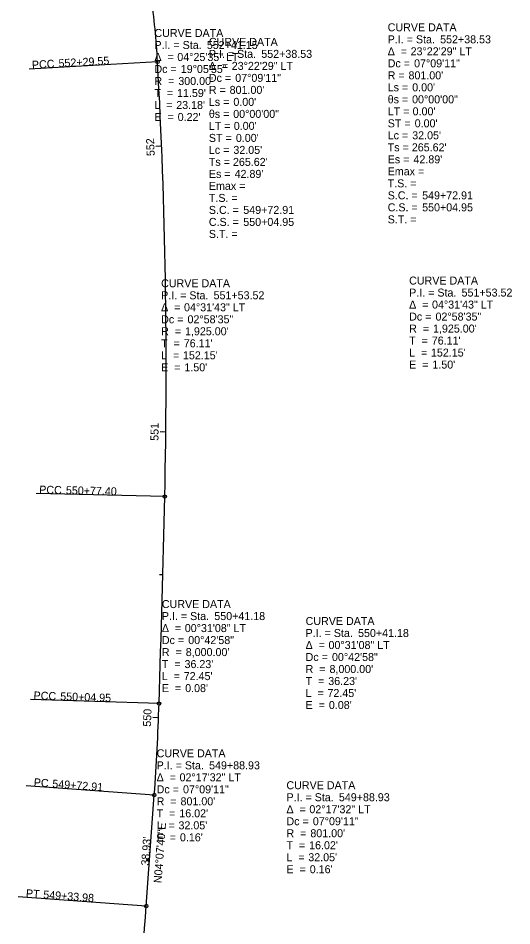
# Model space of a CAD drawing. Extents: x 1922787 to 1923078, y 359089 to 360354.
# Drawn here: x 1922882.9 to 1923055.9, y 359406.6 to 359724.2 of the extents above; entities that cross this region are included whole.
import ezdxf

# ---------------------------------------------------------------- set-up
doc = ezdxf.new("R2010")
doc.units = 0
for name, color, linetype in [('GE_P_Alignment', 7, 'Continuous'), ('GE_P_Alignment_1000_Curve_Data', 7, 'Continuous'), ('GE_P_Alignment_1000_Stations', 7, 'Continuous'), ('GE_P_Alignment_100_Curve_Data', 7, 'Continuous'), ('GE_P_Alignment_100_Stations', 7, 'Continuous'), ('GE_P_Alignment_500_Curve_Data', 7, 'Continuous'), ('GE_P_Alignment_500_Stations', 7, 'Continuous')]:
    doc.layers.add(name, color=color, linetype=linetype)

msp = doc.modelspace()

# ---------------------------------------------------------------- linework, layer by layer
at = {"layer": 'GE_P_Alignment'}
msp.add_line((1922927.81, 359413.55), (1922930.61, 359452.38), dxfattribs=at)
for centre, radius, start, end in [((1922632.22, 359692.09), 300, 3.2119, 7.6383), ((1921009.78, 359601.04), 1925, 358.68333, 3.21194), ((1914936.38, 359740.63), 8000, 358.164444, 358.683333), ((1922131.69, 359510.04), 801, 355.87222, 358.16444), ((1921930.4, 359485.54), 1000, 352.30833, 355.87222)]:
    msp.add_arc(centre, radius, start, end, dxfattribs=at)
at = {"layer": 'GE_P_Alignment_1000_Stations'}
for p, q in [((1922931.75, 359708.9), (1922886.82, 359706.38)), ((1922934.27, 359556.81), (1922889.28, 359557.84)), ((1922932.28, 359484.38), (1922887.3, 359485.83)), ((1922932.1, 359479.44), (1922930.1, 359479.51)), ((1922930.61, 359452.38), (1922885.73, 359455.62)), ((1922927.81, 359413.55), (1922882.92, 359416.79))]:
    msp.add_line(p, q, dxfattribs=at)
for centre in [(1922931.75, 359708.9), (1922934.27, 359556.81), (1922932.28, 359484.38), (1922930.61, 359452.38), (1922927.81, 359413.55)]:
    msp.add_circle(centre, 0.6, dxfattribs=at)
at = {"layer": 'GE_P_Alignment_100_Stations'}
for p, q in [((1922931.75, 359708.9), (1922886.82, 359706.38)), ((1922933.18, 359679.38), (1922931.18, 359679.3)), ((1922934.66, 359579.4), (1922932.66, 359579.42)), ((1922934.27, 359556.81), (1922889.28, 359557.84)), ((1922933.59, 359529.41), (1922932.39, 359529.45)), ((1922932.28, 359484.38), (1922887.3, 359485.83)), ((1922932.1, 359479.44), (1922930.1, 359479.51)), ((1922930.61, 359452.38), (1922885.73, 359455.62)), ((1922928.96, 359429.54), (1922927.76, 359429.62)), ((1922927.81, 359413.55), (1922882.92, 359416.79))]:
    msp.add_line(p, q, dxfattribs=at)
for centre in [(1922931.75, 359708.9), (1922934.27, 359556.81), (1922932.28, 359484.38), (1922930.61, 359452.38), (1922927.81, 359413.55)]:
    msp.add_circle(centre, 0.6, dxfattribs=at)
at = {"layer": 'GE_P_Alignment_500_Stations'}
for p, q in [((1922931.75, 359708.9), (1922886.82, 359706.38)), ((1922933.18, 359679.38), (1922931.98, 359679.33)), ((1922934.66, 359579.4), (1922933.46, 359579.42)), ((1922934.27, 359556.81), (1922889.28, 359557.84)), ((1922932.28, 359484.38), (1922887.3, 359485.83)), ((1922932.1, 359479.44), (1922930.1, 359479.51)), ((1922930.61, 359452.38), (1922885.73, 359455.62)), ((1922927.81, 359413.55), (1922882.92, 359416.79))]:
    msp.add_line(p, q, dxfattribs=at)
for centre in [(1922931.75, 359708.9), (1922934.27, 359556.81), (1922932.28, 359484.38), (1922930.61, 359452.38), (1922927.81, 359413.55)]:
    msp.add_circle(centre, 0.6, dxfattribs=at)

# ---------------------------------------------------------------- texts
at = {"layer": 'GE_P_Alignment_1000_Curve_Data'}
for s, p in [('CURVE DATA', (1922930.66, 359717.63)), ('P.I. = Sta. ', (1922930.66, 359713.43)), ('552+41.15', (1922949.03, 359713.43)), ('CURVE DATA', (1922949.73, 359714.52)), ('P.I. = Sta. ', (1922949.73, 359710.32)), ('552+38.53', (1922968.1, 359710.32)), ('Δ  = ', (1922930.66, 359709.23)), ('04°25\'35" LT', (1922938.68, 359709.23)), ('Dc = ', (1922930.66, 359705.03)), ('19°05\'55"', (1922939.9, 359705.03)), ('Δ  = ', (1922949.73, 359706.12)), ('23°22\'29" LT', (1922957.75, 359706.12)), ('R  = ', (1922930.66, 359700.83)), ("300.00'", (1922939.03, 359700.83)), ('Dc = ', (1922949.73, 359701.92)), ('07°09\'11"', (1922958.97, 359701.92)), ('R = ', (1922949.73, 359697.72)), ("801.00'", (1922957.01, 359697.72)), ('T  = ', (1922930.66, 359696.63)), ("11.59'", (1922938.59, 359696.63)), ('L  = ', (1922930.66, 359692.43)), ("23.18'", (1922938.3, 359692.43)), ('Ls = ', (1922949.73, 359693.52)), ("0.00'", (1922958.32, 359693.52)), ('E  = ', (1922930.66, 359688.23)), ("0.22'", (1922938.81, 359688.23)), ('θs = ', (1922949.73, 359689.32)), ('00°00\'00"', (1922958.26, 359689.32)), ('LT = ', (1922949.73, 359685.12)), ("0.00'", (1922958.46, 359685.12)), ('ST = ', (1922949.73, 359680.92)), ("0.00'", (1922959.19, 359680.92)), ('Lc = ', (1922949.73, 359676.72)), ("32.05'", (1922958.32, 359676.72)), ('Ts = ', (1922949.73, 359672.52)), ("265.62'", (1922958.17, 359672.52)), ('Es = ', (1922949.73, 359668.32)), ("42.89'", (1922958.75, 359668.32)), ('Emax = ', (1922949.73, 359664.12)), ('T.S. = ', (1922949.73, 359659.92)), ('S.C. = ', (1922949.73, 359655.72)), ('549+72.91', (1922961.79, 359655.72)), ('C.S. = ', (1922949.73, 359651.52)), ('550+04.95', (1922961.79, 359651.52)), ('S.T. = ', (1922949.73, 359647.32)), ('CURVE DATA', (1922933.01, 359630.05)), ('P.I. = Sta. ', (1922933.01, 359625.85)), ('551+53.52', (1922951.38, 359625.85)), ('Δ  = ', (1922933.01, 359621.65)), ('04°31\'43" LT', (1922941.03, 359621.65)), ('02°58\'35"', (1922942.25, 359617.45)), ('Dc = ', (1922933.01, 359617.45)), ('R  = ', (1922933.01, 359613.25)), ("1,925.00'", (1922941.38, 359613.25)), ('T  = ', (1922933.01, 359609.05)), ("76.11'", (1922940.94, 359609.05)), ('L  = ', (1922933.01, 359604.85)), ("152.15'", (1922940.66, 359604.85)), ('E  = ', (1922933.01, 359600.65)), ("1.50'", (1922941.16, 359600.65)), ('CURVE DATA', (1922933.27, 359517.8)), ('P.I. = Sta. ', (1922933.27, 359513.6)), ('550+41.18', (1922951.64, 359513.6)), ('Δ  = ', (1922933.27, 359509.4)), ('00°31\'08" LT', (1922941.3, 359509.4)), ('Dc = ', (1922933.27, 359505.2)), ('00°42\'58"', (1922942.51, 359505.2)), ('R  = ', (1922933.27, 359501)), ("8,000.00'", (1922941.64, 359501)), ('T  = ', (1922933.27, 359496.8)), ("36.23'", (1922941.21, 359496.8)), ('L  = ', (1922933.27, 359492.6)), ("72.45'", (1922940.92, 359492.6)), ('E  = ', (1922933.27, 359488.4)), ("0.08'", (1922941.43, 359488.4)), ('CURVE DATA', (1922931.44, 359465.58)), ('P.I. = Sta. ', (1922931.44, 359461.38)), ('549+88.93', (1922949.81, 359461.38)), ('Δ  = ', (1922931.44, 359457.18)), ('02°17\'32" LT', (1922939.47, 359457.18)), ('Dc = ', (1922931.44, 359452.98)), ('07°09\'11"', (1922940.68, 359452.98)), ('R  = ', (1922931.44, 359448.78)), ("801.00'", (1922939.81, 359448.78)), ('T  = ', (1922931.44, 359444.58)), ("16.02'", (1922939.38, 359444.58)), ('L  = ', (1922931.44, 359440.38)), ("32.05'", (1922939.09, 359440.38)), ('E  = ', (1922931.44, 359436.18)), ("0.16'", (1922939.6, 359436.18))]:
    msp.add_text(s, height=2.8, dxfattribs=at).set_placement(p)
for s, p in [('N04°07\'40"E', (1922933.19, 359421.47)), ("38.93'", (1922928.77, 359427.59))]:
    msp.add_text(s, height=2.8, rotation=85.8722, dxfattribs=at).set_placement(p)
at = {"layer": 'GE_P_Alignment_1000_Stations'}
for s, rotation, p in [('PCC', 3.2119, (1922887.82, 359706.48)), ('552+29.55', 3.2119, (1922897.15, 359707)), ('PCC', 358.6833, (1922890.29, 359557.86)), ('550+77.40', 358.6833, (1922899.64, 359557.65)), ('PCC', 358.1644, (1922888.3, 359485.84)), ('550+04.95', 358.1644, (1922897.64, 359485.54)), ('550', 87.8103, (1922929.43, 359476.26)), ('PC', 355.8722, (1922888.32, 359455.48)), ('549+72.91', 355.8722, (1922894.82, 359455.01)), ('PT', 355.8722, (1922885.57, 359416.65)), ('549+33.98', 355.8722, (1922891.64, 359416.21))]:
    msp.add_text(s, height=2.8, rotation=rotation, dxfattribs=at).set_placement(p)
at = {"layer": 'GE_P_Alignment_100_Curve_Data'}
for s, p in [('CURVE DATA', (1923012.37, 359719.62)), ('P.I. = Sta. ', (1923012.37, 359715.42)), ('552+38.53', (1923030.74, 359715.42)), ('Δ  = ', (1923012.37, 359711.22)), ('23°22\'29" LT', (1923020.4, 359711.22)), ('Dc = ', (1923012.37, 359707.02)), ('07°09\'11"', (1923021.61, 359707.02)), ('R = ', (1923012.37, 359702.82)), ("801.00'", (1923019.66, 359702.82)), ('Ls = ', (1923012.37, 359698.62)), ("0.00'", (1923020.96, 359698.62)), ('θs = ', (1923012.37, 359694.42)), ('00°00\'00"', (1923020.91, 359694.42)), ('LT = ', (1923012.37, 359690.22)), ("0.00'", (1923021.1, 359690.22)), ('ST = ', (1923012.37, 359686.02)), ("0.00'", (1923021.83, 359686.02)), ('Lc = ', (1923012.37, 359681.82)), ("32.05'", (1923020.96, 359681.82)), ('Ts = ', (1923012.37, 359677.62)), ("265.62'", (1923020.82, 359677.62)), ('Es = ', (1923012.37, 359673.42)), ("42.89'", (1923021.4, 359673.42)), ('Emax = ', (1923012.37, 359669.22)), ('T.S. = ', (1923012.37, 359665.02)), ('S.C. = ', (1923012.37, 359660.82)), ('549+72.91', (1923024.44, 359660.82)), ('C.S. = ', (1923012.37, 359656.62)), ('550+04.95', (1923024.44, 359656.62)), ('S.T. = ', (1923012.37, 359652.42)), ('CURVE DATA', (1923019.88, 359631)), ('P.I. = Sta. ', (1923019.88, 359626.8)), ('551+53.52', (1923038.25, 359626.8)), ('Δ  = ', (1923019.88, 359622.6)), ('04°31\'43" LT', (1923027.9, 359622.6)), ('Dc = ', (1923019.88, 359618.4)), ('02°58\'35"', (1923029.12, 359618.4)), ('R  = ', (1923019.88, 359614.2)), ("1,925.00'", (1923028.25, 359614.2)), ('T  = ', (1923019.88, 359610)), ("76.11'", (1923027.81, 359610)), ('L  = ', (1923019.88, 359605.8)), ("152.15'", (1923027.53, 359605.8)), ('E  = ', (1923019.88, 359601.6)), ("1.50'", (1923028.03, 359601.6)), ('CURVE DATA', (1922983.62, 359511.87)), ('P.I. = Sta. ', (1922983.62, 359507.67)), ('550+41.18', (1923001.99, 359507.67)), ('Δ  = ', (1922983.62, 359503.47)), ('00°31\'08" LT', (1922991.64, 359503.47)), ('Dc = ', (1922983.62, 359499.27)), ('00°42\'58"', (1922992.86, 359499.27)), ('R  = ', (1922983.62, 359495.07)), ("8,000.00'", (1922991.99, 359495.07)), ('T  = ', (1922983.62, 359490.87)), ("36.23'", (1922991.55, 359490.87)), ('L  = ', (1922983.62, 359486.67)), ("72.45'", (1922991.27, 359486.67)), ('E  = ', (1922983.62, 359482.47)), ("0.08'", (1922991.77, 359482.47)), ('CURVE DATA', (1922976.91, 359454.41)), ('P.I. = Sta. ', (1922976.91, 359450.21)), ('549+88.93', (1922995.28, 359450.21)), ('Δ  = ', (1922976.91, 359446.01)), ('02°17\'32" LT', (1922984.94, 359446.01)), ('Dc = ', (1922976.91, 359441.81)), ('07°09\'11"', (1922986.15, 359441.81)), ('R  = ', (1922976.91, 359437.61)), ("801.00'", (1922985.28, 359437.61)), ('T  = ', (1922976.91, 359433.41)), ("16.02'", (1922984.85, 359433.41)), ('L  = ', (1922976.91, 359429.21)), ("32.05'", (1922984.56, 359429.21)), ('E  = ', (1922976.91, 359425.01)), ("0.16'", (1922985.07, 359425.01))]:
    msp.add_text(s, height=2.8, dxfattribs=at).set_placement(p)
for s, p in [('N04°07\'40"E', (1922933.19, 359421.47)), ("38.93'", (1922928.77, 359427.59))]:
    msp.add_text(s, height=2.8, rotation=85.8722, dxfattribs=at).set_placement(p)
at = {"layer": 'GE_P_Alignment_100_Stations'}
for s, rotation, p in [('PCC', 3.2119, (1922887.82, 359706.48)), ('552+29.55', 3.2119, (1922897.15, 359707)), ('552', 92.3324, (1922930.77, 359676.01)), ('551', 89.356, (1922932.07, 359576.32)), ('PCC', 358.6833, (1922890.29, 359557.86)), ('550+77.40', 358.6833, (1922899.64, 359557.65)), ('PCC', 358.1644, (1922888.3, 359485.84)), ('550+04.95', 358.1644, (1922897.64, 359485.54)), ('550', 87.8103, (1922929.43, 359476.26)), ('PC', 355.8722, (1922888.32, 359455.48)), ('549+72.91', 355.8722, (1922894.82, 359455.01)), ('PT', 355.8722, (1922885.57, 359416.65)), ('549+33.98', 355.8722, (1922891.64, 359416.21))]:
    msp.add_text(s, height=2.8, rotation=rotation, dxfattribs=at).set_placement(p)
at = {"layer": 'GE_P_Alignment_500_Curve_Data'}
for s, p in [('CURVE DATA', (1922930.66, 359717.63)), ('P.I. = Sta. ', (1922930.66, 359713.43)), ('552+41.15', (1922949.03, 359713.43)), ('CURVE DATA', (1922949.73, 359714.52)), ('P.I. = Sta. ', (1922949.73, 359710.32)), ('552+38.53', (1922968.1, 359710.32)), ('Δ  = ', (1922930.66, 359709.23)), ('04°25\'35" LT', (1922938.68, 359709.23)), ('Dc = ', (1922930.66, 359705.03)), ('19°05\'55"', (1922939.9, 359705.03)), ('Δ  = ', (1922949.73, 359706.12)), ('23°22\'29" LT', (1922957.75, 359706.12)), ('R  = ', (1922930.66, 359700.83)), ("300.00'", (1922939.03, 359700.83)), ('Dc = ', (1922949.73, 359701.92)), ('07°09\'11"', (1922958.97, 359701.92)), ('R = ', (1922949.73, 359697.72)), ("801.00'", (1922957.01, 359697.72)), ('T  = ', (1922930.66, 359696.63)), ("11.59'", (1922938.59, 359696.63)), ('L  = ', (1922930.66, 359692.43)), ("23.18'", (1922938.3, 359692.43)), ('Ls = ', (1922949.73, 359693.52)), ("0.00'", (1922958.32, 359693.52)), ('E  = ', (1922930.66, 359688.23)), ("0.22'", (1922938.81, 359688.23)), ('θs = ', (1922949.73, 359689.32)), ('00°00\'00"', (1922958.26, 359689.32)), ('LT = ', (1922949.73, 359685.12)), ("0.00'", (1922958.46, 359685.12)), ('ST = ', (1922949.73, 359680.92)), ("0.00'", (1922959.19, 359680.92)), ('Lc = ', (1922949.73, 359676.72)), ("32.05'", (1922958.32, 359676.72)), ('Ts = ', (1922949.73, 359672.52)), ("265.62'", (1922958.17, 359672.52)), ('Es = ', (1922949.73, 359668.32)), ("42.89'", (1922958.75, 359668.32)), ('Emax = ', (1922949.73, 359664.12)), ('T.S. = ', (1922949.73, 359659.92)), ('S.C. = ', (1922949.73, 359655.72)), ('549+72.91', (1922961.79, 359655.72)), ('C.S. = ', (1922949.73, 359651.52)), ('550+04.95', (1922961.79, 359651.52)), ('S.T. = ', (1922949.73, 359647.32)), ('CURVE DATA', (1922933.01, 359630.05)), ('P.I. = Sta. ', (1922933.01, 359625.85)), ('551+53.52', (1922951.38, 359625.85)), ('Δ  = ', (1922933.01, 359621.65)), ('04°31\'43" LT', (1922941.03, 359621.65)), ('02°58\'35"', (1922942.25, 359617.45)), ('Dc = ', (1922933.01, 359617.45)), ('R  = ', (1922933.01, 359613.25)), ("1,925.00'", (1922941.38, 359613.25)), ('T  = ', (1922933.01, 359609.05)), ("76.11'", (1922940.94, 359609.05)), ('L  = ', (1922933.01, 359604.85)), ("152.15'", (1922940.66, 359604.85)), ('E  = ', (1922933.01, 359600.65)), ("1.50'", (1922941.16, 359600.65)), ('CURVE DATA', (1922933.27, 359517.8)), ('P.I. = Sta. ', (1922933.27, 359513.6)), ('550+41.18', (1922951.64, 359513.6)), ('Δ  = ', (1922933.27, 359509.4)), ('00°31\'08" LT', (1922941.3, 359509.4)), ('Dc = ', (1922933.27, 359505.2)), ('00°42\'58"', (1922942.51, 359505.2)), ('R  = ', (1922933.27, 359501)), ("8,000.00'", (1922941.64, 359501)), ('T  = ', (1922933.27, 359496.8)), ("36.23'", (1922941.21, 359496.8)), ('L  = ', (1922933.27, 359492.6)), ("72.45'", (1922940.92, 359492.6)), ('E  = ', (1922933.27, 359488.4)), ("0.08'", (1922941.43, 359488.4)), ('CURVE DATA', (1922931.44, 359465.58)), ('P.I. = Sta. ', (1922931.44, 359461.38)), ('549+88.93', (1922949.81, 359461.38)), ('Δ  = ', (1922931.44, 359457.18)), ('02°17\'32" LT', (1922939.47, 359457.18)), ('Dc = ', (1922931.44, 359452.98)), ('07°09\'11"', (1922940.68, 359452.98)), ('R  = ', (1922931.44, 359448.78)), ("801.00'", (1922939.81, 359448.78)), ('T  = ', (1922931.44, 359444.58)), ("16.02'", (1922939.38, 359444.58)), ('L  = ', (1922931.44, 359440.38)), ("32.05'", (1922939.09, 359440.38)), ('E  = ', (1922931.44, 359436.18)), ("0.16'", (1922939.6, 359436.18))]:
    msp.add_text(s, height=2.8, dxfattribs=at).set_placement(p)
for s, p in [('N04°07\'40"E', (1922933.19, 359421.47)), ("38.93'", (1922928.77, 359427.59))]:
    msp.add_text(s, height=2.8, rotation=85.8722, dxfattribs=at).set_placement(p)
at = {"layer": 'GE_P_Alignment_500_Stations'}
for s, rotation, p in [('PCC', 3.2119, (1922887.82, 359706.48)), ('552+29.55', 3.2119, (1922897.15, 359707)), ('PCC', 358.6833, (1922890.29, 359557.86)), ('550+77.40', 358.6833, (1922899.64, 359557.65)), ('PCC', 358.1644, (1922888.3, 359485.84)), ('550+04.95', 358.1644, (1922897.64, 359485.54)), ('550', 87.8103, (1922929.43, 359476.26)), ('PC', 355.8722, (1922888.32, 359455.48)), ('549+72.91', 355.8722, (1922894.82, 359455.01)), ('PT', 355.8722, (1922885.57, 359416.65)), ('549+33.98', 355.8722, (1922891.64, 359416.21))]:
    msp.add_text(s, height=2.8, rotation=rotation, dxfattribs=at).set_placement(p)

doc.saveas('drawing.dxf')
